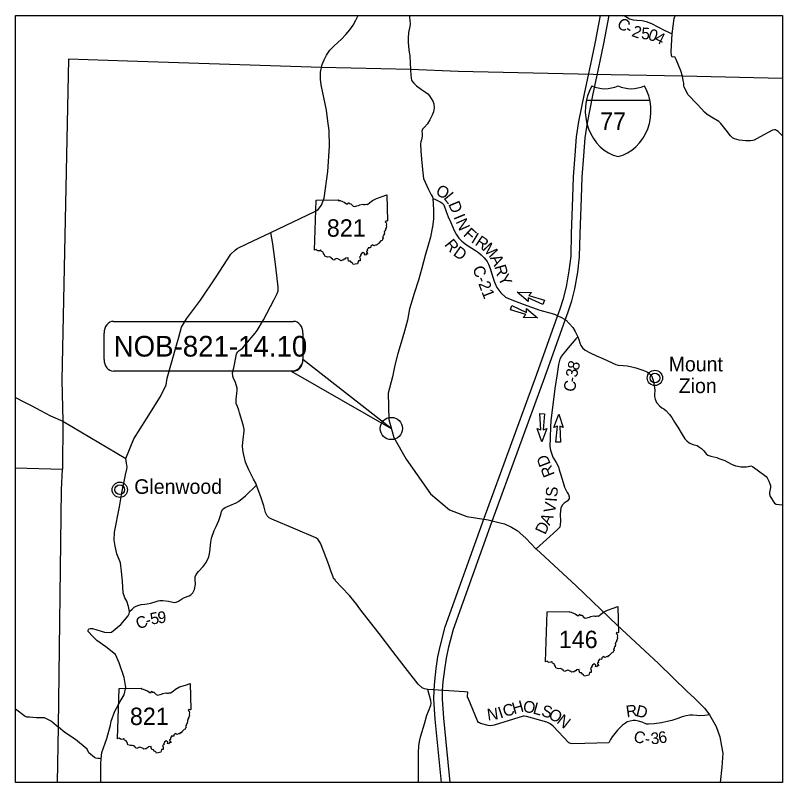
# Model space of a CAD drawing. Extents: x -452339 to 6403467, y -1 to 1814750.
# Drawn here: x 53877 to 93371, y 1551166 to 1590661 of the extents above; entities that cross this region are included whole.
import ezdxf

# ---------------------------------------------------------------- set-up
doc = ezdxf.new("R2010")
doc.units = 0
for name, color, linetype in [('Default', 7, 'Continuous'), ('GM_X_Adjacent_County_Text', 7, 'Continuous'), ('GM_X_County', 7, 'Continuous'), ('GM_X_County_Road', 7, 'Continuous'), ('GM_X_County_Road_Text', 7, 'Continuous'), ('GM_X_Minor_Lake_Text', 7, 'Continuous'), ('GM_X_Section_Text', 7, 'Continuous'), ('GM_X_Township_ROW', 7, 'Continuous')]:
    doc.layers.add(name, color=color, linetype=linetype)

msp = doc.modelspace()

# ---------------------------------------------------------------- linework, layer by layer
at = {"layer": 'Default'}
for p, q in [((53877, 1551166), (53877, 1590661)), ((53877, 1590661), (93371, 1590661)), ((93371, 1590661), (93371, 1551166)), ((69279, 1578571), (69362, 1581153)), ((79709, 1576407), (80444, 1576389)), ((80265, 1575926), (79709, 1576407)), ((80444, 1576389), (80309, 1576239)), ((80309, 1576239), (81106, 1575994)), ((80266, 1576128), (80265, 1575926)), ((81020, 1575773), (80266, 1576128)), ((81106, 1575994), (81020, 1575773)), ((79355, 1575504), (79440, 1575725)), ((80151, 1575258), (79355, 1575504)), ((79440, 1575725), (80195, 1575370)), ((80195, 1575370), (80195, 1575571)), ((80195, 1575571), (80751, 1575090)), ((80015, 1575109), (80151, 1575258)), ((80751, 1575090), (80015, 1575109)), ((80919, 1569326), (80873, 1570159)), ((80873, 1570159), (81110, 1570155)), ((81110, 1570155), (81039, 1569324)), ((81585, 1569451), (81843, 1570140)), ((81843, 1570140), (82082, 1569444)), ((81775, 1569521), (81585, 1569451)), ((81704, 1568690), (81775, 1569521)), ((82082, 1569444), (81894, 1569519)), ((81894, 1569519), (81941, 1568686)), ((80970, 1568706), (80732, 1569402)), ((80732, 1569402), (80919, 1569326)), ((81229, 1569394), (80970, 1568706)), ((81039, 1569324), (81229, 1569394)), ((81941, 1568686), (81704, 1568690)), ((81169, 1557385), (81252, 1559967)), ((59143, 1553424), (59226, 1556006)), ((93371, 1551166), (53877, 1551166))]:
    msp.add_line(p, q, dxfattribs=at)
for points in [[(85210, 1590661), (85358, 1590561), (85481, 1590488), (85671, 1590437), (85874, 1590419), (86133, 1590396), (86352, 1590345), (86618, 1590234), (87276, 1589890), (87684, 1589716)], [(88215, 1587527), (88127, 1587807), (87891, 1588388), (87819, 1588531), (87686, 1588501), (87643, 1588594), (87638, 1588794), (87684, 1589716), (87781, 1590504), (87818, 1590600), (87870, 1590661)], [(93371, 1584462), (93145, 1584676), (93054, 1584741), (93002, 1584766), (92946, 1584770), (92850, 1584743), (92216, 1584401), (91903, 1584244), (91831, 1584217), (91715, 1584202), (91484, 1584200), (91125, 1584240), (90886, 1584302), (90790, 1584359), (90684, 1584460), (90463, 1584758), (90266, 1585013), (90187, 1585101), (90080, 1585191), (89803, 1585361), (89485, 1585565), (89347, 1585678), (89216, 1585827), (88952, 1586114), (88509, 1586567), (88309, 1586966), (88290, 1587041), (88279, 1587162), (88255, 1587300), (88215, 1587527)], [(69362, 1581153), (70507, 1581170), (70489, 1581138), (70597, 1581132), (70711, 1581077), (70809, 1581042), (70927, 1580960), (70998, 1580961), (71028, 1581029), (71082, 1580976), (71147, 1580967), (71259, 1580843), (71351, 1580817), (71462, 1580859), (71544, 1580866), (71604, 1580908), (71761, 1580944), (71805, 1580922), (71888, 1580927), (71931, 1580943), (72003, 1580928), (72130, 1581023), (72262, 1581133), (72464, 1581238), (72766, 1581336), (73005, 1581425), (73040, 1580084)], [(75373, 1581231), (75473, 1581198), (75751, 1581067), (75830, 1581010), (75925, 1580901), (76045, 1580572), (76154, 1580290), (76295, 1579997), (76462, 1579591), (76568, 1579390), (76702, 1579200), (76860, 1579035), (77094, 1578852), (77506, 1578596), (77721, 1578458), (77851, 1578340), (78009, 1578175), (78155, 1577989), (78229, 1577848), (78315, 1577631), (78446, 1577178), (78535, 1576920), (78664, 1576651), (78865, 1576377), (79107, 1576162), (79349, 1576044), (80017, 1575801), (80880, 1575480), (81501, 1575318), (81660, 1575265), (81804, 1575199), (81989, 1575104), (82220, 1574967), (82386, 1574805), (82564, 1574595), (82690, 1574390), (82827, 1574108)], [(73040, 1580084), (73004, 1580066), (72949, 1580075), (72913, 1580038), (72959, 1579975), (72980, 1579908), (72961, 1579836), (72980, 1579775), (72967, 1579725), (72933, 1579674), (72921, 1579627), (72891, 1579576), (72893, 1579548), (72866, 1579526), (72871, 1579442), (72856, 1579396), (72861, 1579356), (72816, 1579345), (72826, 1579312), (72797, 1579286), (72804, 1579242), (72771, 1579214), (72802, 1579158), (72777, 1579140), (72756, 1579072), (72697, 1579058), (72582, 1578933), (72540, 1578886), (72495, 1578874), (72469, 1578825), (72412, 1578825), (72326, 1578791), (72270, 1578849), (72173, 1578780), (72162, 1578699), (72039, 1578701), (72043, 1578661), (72016, 1578649), (71991, 1578608), (72005, 1578536), (71948, 1578517), (71955, 1578475), (71992, 1578450), (72008, 1578369), (71947, 1578385), (71897, 1578318), (71845, 1578334), (71862, 1578391), (71774, 1578461), (71692, 1578405), (71649, 1578316), (71648, 1578257), (71586, 1578221), (71627, 1578137), (71619, 1578079), (71620, 1578024), (71544, 1578026), (71496, 1577878)], [(66283, 1566486), (66259, 1566574), (66141, 1566786), (65894, 1567272), (65731, 1567667), (65620, 1568111), (65583, 1568295), (65566, 1568495), (65595, 1568836), (65652, 1569269), (65655, 1569357), (65602, 1569585), (65410, 1570204), (65373, 1570344), (65307, 1570532), (65250, 1570683), (65246, 1570795), (65249, 1570912), (65283, 1571192), (65302, 1571365), (65293, 1571477), (65268, 1571593), (65186, 1571816), (65101, 1571972), (65077, 1572094), (65055, 1572255), (65118, 1572518), (65268, 1573225), (65285, 1573269), (65329, 1573337), (65402, 1573404), (65490, 1573468), (65591, 1573543), (65724, 1573713), (66213, 1574297), (66331, 1574440), (66655, 1574986), (67189, 1576001), (67360, 1576352), (67397, 1576484), (67399, 1576668), (67290, 1577710), (67126, 1578900), (67019, 1579488)], [(71496, 1577878), (71363, 1577850), (71271, 1577833), (71238, 1577900), (71172, 1577936), (71128, 1578003), (71033, 1578012), (71011, 1578106), (71000, 1578181), (70870, 1578162), (70835, 1578116), (70788, 1578104), (70761, 1578057), (70698, 1578053), (70630, 1578031), (70586, 1578077), (70476, 1578123), (70426, 1578146), (70321, 1578110), (70300, 1578066), (70217, 1578085), (70197, 1578134), (70147, 1578149), (70136, 1578200), (70029, 1578228), (69947, 1578217), (69803, 1578258), (69793, 1578326), (69744, 1578408), (69719, 1578466), (69628, 1578509), (69609, 1578577), (69580, 1578575), (69553, 1578547), (69451, 1578535), (69411, 1578562), (69354, 1578610), (69279, 1578571)], [(82827, 1574108), (82730, 1574009), (82245, 1573445), (82205, 1573399)], [(82827, 1574108), (82873, 1573980), (82931, 1573803), (82986, 1573674), (83064, 1573542), (83203, 1573424), (83461, 1573289), (83791, 1573134), (84117, 1572995), (84597, 1572770), (84788, 1572688), (84904, 1572659), (85155, 1572632), (85366, 1572618), (85546, 1572589), (85812, 1572510), (86123, 1572419), (86306, 1572341), (86413, 1572292), (86486, 1572245), (86558, 1572168), (86639, 1572082), (86671, 1571977), (86700, 1571883)], [(82205, 1573399), (82204, 1573398), (82087, 1573263), (81982, 1573112), (81905, 1572956), (81830, 1572693), (81773, 1572209), (81645, 1571448), (81512, 1570344), (81445, 1569802), (81415, 1569473), (81408, 1568936), (81396, 1568467), (81424, 1568272), (81550, 1567917), (81718, 1567652), (81826, 1567422), (81873, 1567274), (81941, 1567055), (82068, 1566617), (82144, 1566370), (82277, 1566108), (82347, 1566001), (82384, 1565877), (82383, 1565778), (82277, 1565655), (82130, 1565553), (82048, 1565463), (81951, 1565305), (81912, 1564992), (81935, 1564616), (81926, 1564448), (81900, 1564311), (81750, 1564164), (80689, 1563193)], [(86700, 1571883), (86726, 1571776), (86767, 1571504), (86786, 1571348), (86777, 1571144), (86775, 1571044), (86805, 1570900), (86884, 1570729), (87051, 1570552), (87161, 1570466), (87258, 1570407), (87359, 1570321), (87555, 1570112), (87666, 1569954), (87806, 1569728), (87974, 1569467), (88201, 1569090), (88340, 1568865), (88434, 1568758), (88552, 1568656), (88750, 1568564), (88970, 1568512), (89043, 1568477), (89201, 1568363), (89307, 1568249), (89376, 1568162), (89434, 1568083), (89523, 1568029), (89680, 1567968), (89985, 1567897), (90094, 1567855), (90391, 1567740), (90735, 1567554), (90944, 1567466), (91068, 1567452), (91225, 1567419), (91517, 1567424), (91680, 1567459), (91736, 1567468), (91817, 1567433), (92056, 1567261), (92517, 1566921), (92578, 1566858), (92665, 1566691), (92716, 1566552), (92741, 1566468), (92743, 1566356), (92706, 1566191), (92691, 1566103), (92697, 1566019), (92727, 1565903), (92957, 1565559), (93042, 1565505), (93186, 1565479), (93371, 1565463)], [(59746, 1559984), (59891, 1560096), (59999, 1560196), (60054, 1560241), (60178, 1560290), (60361, 1560340), (60549, 1560353), (60661, 1560370), (60857, 1560408), (61232, 1560523), (61320, 1560539), (61475, 1560541), (61756, 1560507), (61988, 1560453), (62072, 1560445), (62152, 1560454), (62275, 1560507), (62430, 1560608), (62586, 1560698), (62817, 1560788), (62917, 1560836), (63016, 1560933), (63091, 1561114), (63149, 1561387), (63131, 1561603), (63138, 1561755), (63185, 1561888), (63304, 1562029), (63542, 1562299), (63701, 1562493), (63830, 1562786), (63881, 1563043), (63933, 1563544), (63976, 1563756), (64105, 1564138), (64207, 1564351), (64353, 1564653), (64447, 1564974), (64482, 1565122), (64557, 1565235), (64672, 1565328), (64911, 1565426), (65238, 1565565), (65370, 1565638), (65719, 1565933), (66283, 1566486)], [(77176, 1555508), (77176, 1555510), (77155, 1555559), (77147, 1555611), (77161, 1555823), (76993, 1555838), (75649, 1555922), (75113, 1555955), (74945, 1555998), (74824, 1556053), (74619, 1556243), (73942, 1557099), (73308, 1557919), (72606, 1558839), (71775, 1559894), (71561, 1560184), (71452, 1560328), (71307, 1560531), (71081, 1560805), (70678, 1561219), (70364, 1561557), (70332, 1561600), (70259, 1561672), (70235, 1561764), (70133, 1562019), (70018, 1562375), (69733, 1563102), (69575, 1563497), (69518, 1563604), (69453, 1563696), (69349, 1563767), (68298, 1564215), (67079, 1564726), (66947, 1564801), (66830, 1564897), (66745, 1565076), (66659, 1565420), (66536, 1565831), (66365, 1566295), (66283, 1566486)], [(81252, 1559967), (82397, 1559984), (82380, 1559952), (82487, 1559946), (82602, 1559891), (82699, 1559856), (82817, 1559774), (82889, 1559775), (82919, 1559842), (82973, 1559790), (83038, 1559781), (83150, 1559657), (83242, 1559631), (83353, 1559673), (83434, 1559680), (83495, 1559722), (83652, 1559757), (83696, 1559736), (83779, 1559741), (83821, 1559756), (83894, 1559742), (84021, 1559836), (84152, 1559947), (84355, 1560051), (84656, 1560150), (84896, 1560239), (84930, 1558898)], [(84930, 1558898), (84895, 1558880), (84840, 1558888), (84803, 1558851), (84849, 1558788), (84870, 1558722), (84851, 1558649), (84870, 1558589), (84858, 1558538), (84823, 1558488), (84811, 1558440), (84782, 1558390), (84784, 1558362), (84756, 1558340), (84761, 1558256), (84747, 1558209), (84752, 1558169), (84706, 1558159), (84717, 1558126), (84688, 1558100), (84694, 1558056), (84661, 1558028), (84693, 1557972), (84668, 1557954), (84646, 1557885), (84588, 1557871), (84473, 1557747), (84431, 1557699), (84385, 1557688), (84359, 1557639), (84303, 1557639), (84216, 1557605), (84161, 1557663), (84064, 1557593), (84052, 1557513), (83930, 1557515), (83934, 1557475), (83907, 1557463), (83882, 1557422), (83896, 1557350), (83838, 1557331), (83845, 1557289), (83883, 1557264), (83899, 1557183), (83838, 1557199), (83788, 1557131), (83735, 1557147), (83752, 1557205), (83665, 1557274), (83583, 1557219), (83540, 1557130), (83539, 1557070), (83477, 1557035), (83517, 1556951), (83510, 1556893), (83511, 1556838), (83434, 1556840), (83387, 1556692)], [(83387, 1556692), (83254, 1556663), (83162, 1556647), (83129, 1556714), (83062, 1556750), (83019, 1556817), (82924, 1556826), (82901, 1556920), (82891, 1556995), (82760, 1556976), (82725, 1556930), (82679, 1556918), (82652, 1556871), (82589, 1556867), (82521, 1556845), (82477, 1556891), (82366, 1556937), (82316, 1556960), (82212, 1556924), (82190, 1556880), (82108, 1556899), (82088, 1556948), (82038, 1556963), (82027, 1557014), (81920, 1557042), (81838, 1557030), (81693, 1557072), (81684, 1557139), (81635, 1557222), (81610, 1557279), (81519, 1557322), (81500, 1557391), (81471, 1557389), (81444, 1557361), (81342, 1557348), (81302, 1557376), (81245, 1557424), (81169, 1557385)], [(59226, 1556006), (60371, 1556023), (60353, 1555991), (60461, 1555985), (60576, 1555930), (60673, 1555895), (60791, 1555813), (60862, 1555814), (60893, 1555882), (60947, 1555829), (61012, 1555820), (61123, 1555696), (61216, 1555670), (61326, 1555712), (61408, 1555719), (61468, 1555761), (61625, 1555797), (61670, 1555775), (61753, 1555780), (61795, 1555795), (61868, 1555781), (61994, 1555875), (62126, 1555986), (62329, 1556090), (62630, 1556189), (62869, 1556278), (62904, 1554937)], [(74630, 1551166), (74623, 1551758), (74636, 1552699), (74650, 1553068), (74684, 1553284), (74754, 1553577), (74937, 1554199), (75062, 1554645), (75145, 1554838), (75267, 1555151), (75286, 1555251), (75265, 1555395), (75175, 1555707), (75113, 1555955)], [(89606, 1554657), (89360, 1554625), (89104, 1554611), (88960, 1554622), (88748, 1554644), (88596, 1554639), (88412, 1554613), (88205, 1554560), (87982, 1554474), (87662, 1554363), (87423, 1554313), (87132, 1554239), (86756, 1554192), (86460, 1554170), (86360, 1554185), (86132, 1554283), (85955, 1554338), (85803, 1554365), (85675, 1554360), (85528, 1554335), (85376, 1554289), (85276, 1554236), (85125, 1554123), (84879, 1553873), (84590, 1553522), (84507, 1553385), (84452, 1553285), (84420, 1553208), (82569, 1553166), (82469, 1553177), (82369, 1553220), (81555, 1554071), (81463, 1554163), (81378, 1554214), (81230, 1554285), (80180, 1554577), (80072, 1554592), (80008, 1554584), (78524, 1554131), (78357, 1554098), (78213, 1554101), (77824, 1554206), (77772, 1554238), (77723, 1554265), (77659, 1554353), (77176, 1555508)], [(53877, 1554959), (54379, 1554594), (54448, 1554555), (54612, 1554554), (54957, 1554512), (55356, 1554515), (55744, 1554329), (56091, 1554024)], [(62904, 1554937), (62869, 1554919), (62814, 1554927), (62777, 1554890), (62823, 1554828), (62844, 1554761), (62825, 1554688), (62844, 1554628), (62831, 1554577), (62797, 1554527), (62785, 1554480), (62755, 1554429), (62757, 1554401), (62730, 1554379), (62735, 1554295), (62721, 1554249), (62726, 1554208), (62680, 1554198), (62691, 1554165), (62662, 1554139), (62668, 1554095), (62635, 1554067), (62667, 1554011), (62641, 1553993), (62620, 1553925), (62562, 1553910), (62446, 1553786), (62405, 1553738), (62359, 1553727), (62333, 1553678), (62277, 1553678), (62190, 1553644), (62134, 1553702), (62037, 1553633), (62026, 1553552), (61903, 1553554), (61908, 1553514), (61880, 1553502), (61856, 1553461), (61870, 1553389), (61812, 1553370), (61819, 1553328), (61856, 1553303), (61873, 1553222), (61811, 1553238), (61761, 1553171), (61709, 1553187), (61726, 1553244), (61639, 1553313), (61556, 1553258), (61513, 1553169), (61513, 1553110), (61451, 1553074), (61491, 1552990), (61483, 1552932), (61485, 1552877), (61408, 1552879), (61361, 1552731)], [(58298, 1552388), (58188, 1552408), (58122, 1552414), (58018, 1552427), (57950, 1552459), (57656, 1552697), (57576, 1552896), (56966, 1553387), (56419, 1553752), (56091, 1554024)], [(61361, 1552731), (61228, 1552702), (61135, 1552686), (61102, 1552753), (61036, 1552789), (60993, 1552856), (60897, 1552865), (60875, 1552959), (60864, 1553034), (60734, 1553015), (60699, 1552969), (60652, 1552957), (60626, 1552910), (60562, 1552906), (60495, 1552884), (60450, 1552930), (60340, 1552976), (60290, 1552999), (60186, 1552963), (60164, 1552919), (60082, 1552938), (60062, 1552987), (60012, 1553002), (60001, 1553053), (59894, 1553081), (59811, 1553070), (59667, 1553111), (59658, 1553179), (59608, 1553261), (59584, 1553318), (59492, 1553361), (59473, 1553430), (59444, 1553428), (59418, 1553400), (59316, 1553387), (59275, 1553415), (59218, 1553463), (59143, 1553424)]]:
    msp.add_lwpolyline(points, dxfattribs=at)
for centre, major_axis, start_param, end_param in [((85392, 1585748), (0, -2422), 4.15077, 6.05619), ((84224, 1588818), (0, -1932), 5.88324, 6.683049), ((84411, 1585748), (0, -2422), 0.227007, 2.13242), ((85578, 1588819), (0, -1933), 5.883359, 6.683012)]:
    msp.add_ellipse(centre, major_axis=major_axis, ratio=0.9, start_param=start_param, end_param=end_param, dxfattribs=at)
at = {"layer": 'GM_X_County_Road'}
for points in [[(69631, 1587971), (69670, 1588131), (69765, 1588372), (69886, 1588617), (70066, 1588868), (70281, 1589098), (70667, 1589434), (70887, 1589674), (71088, 1589915), (71258, 1590155), (71404, 1590410), (71526, 1590661)], [(74144, 1590661), (74167, 1590564), (74197, 1590217), (74179, 1590085), (74119, 1589775), (74089, 1589494), (74098, 1589258), (74138, 1588878), (74183, 1588557), (74223, 1587875)], [(83397, 1587667), (83554, 1588393), (83730, 1589294), (83904, 1590204), (84001, 1590661)], [(83827, 1587574), (83985, 1588305), (84162, 1589211), (84439, 1590661)], [(59565, 1567850), (59978, 1568862), (60623, 1569900), (61344, 1571042), (61634, 1571649), (61689, 1571994), (62168, 1573691), (62286, 1574096), (62437, 1574614), (62693, 1575047), (63414, 1576007), (64219, 1577195), (64969, 1578369), (65187, 1578579), (65287, 1578658), (65785, 1578905), (67019, 1579488), (69287, 1580557), (69461, 1580675), (69643, 1580898), (69779, 1581248), (69957, 1582622), (70048, 1583926), (70032, 1584733), (69967, 1585209), (69886, 1585785), (69613, 1587090), (69580, 1587368), (69576, 1587556), (69591, 1587741), (69631, 1587971)], [(74223, 1587875), (74238, 1587571), (74245, 1587467), (74251, 1587409), (74263, 1587344), (74283, 1587288), (74383, 1587164), (74532, 1587026), (74790, 1586847), (74988, 1586714), (75100, 1586625), (75191, 1586518), (75280, 1586384), (75360, 1586245), (75413, 1586098), (75436, 1585902), (75405, 1585702), (75338, 1585519), (75212, 1585280), (75096, 1585085), (74942, 1584909), (74838, 1584802), (74803, 1584704), (74813, 1584569), (74810, 1584434), (74778, 1584258), (74753, 1584154), (74731, 1584041), (74750, 1583685), (74785, 1583256), (74829, 1582721), (74890, 1582268), (75059, 1581881), (75150, 1581697), (75283, 1581428), (75342, 1581327), (75373, 1581231), (75399, 1580654), (75403, 1580187), (75344, 1579755), (75344, 1579752)], [(78008, 1564774), (80722, 1572188), (81782, 1575177), (81914, 1575551), (82099, 1576085), (82249, 1576682), (82390, 1577503), (82480, 1578262), (82510, 1579426), (82575, 1581277), (82607, 1582352), (82699, 1583466), (82761, 1584400), (82888, 1585205), (83175, 1586625), (83397, 1587667)], [(78421, 1564622), (81136, 1572039), (82196, 1575030), (82330, 1575406), (82521, 1575959), (82680, 1576591), (82825, 1577440), (82919, 1578230), (82950, 1579413), (83015, 1581263), (83046, 1582327), (83137, 1583434), (83199, 1584351), (83321, 1585128), (83606, 1586535), (83828, 1587575)], [(75344, 1579752), (75337, 1579702), (75246, 1579248), (74965, 1578300), (74793, 1577649), (74621, 1577026), (74401, 1576338), (74235, 1575775), (74170, 1575555), (74053, 1574972), (73908, 1574410), (73739, 1573815), (73569, 1573256), (73413, 1572654), (73296, 1572048), (73070, 1571221), (73105, 1569860), (73353, 1568931), (73989, 1567817), (75239, 1566025), (76221, 1565210), (77107, 1564869), (78215, 1564698), (78832, 1564536), (79059, 1564490), (79412, 1564310), (79701, 1564144), (80147, 1563753), (80674, 1563207), (80689, 1563193), (82745, 1561292), (84852, 1559278), (86987, 1557300), (86999, 1557288), (88455, 1555855), (88814, 1555538), (89373, 1554985), (89606, 1554657), (89879, 1554184), (89952, 1554057), (90131, 1553527), (90229, 1553041), (90290, 1552685), (90233, 1551955), (90156, 1551166)], [(53877, 1570985), (54308, 1570770), (54718, 1570559), (55180, 1570313), (55678, 1570043), (56319, 1569768)], [(56319, 1569768), (59565, 1567850)], [(58284, 1551166), (58271, 1551875), (58277, 1552152), (58298, 1552388), (58328, 1552717), (58582, 1553440), (58776, 1554118), (58803, 1554334), (59005, 1554845), (59267, 1555348), (59471, 1555685), (59558, 1556063), (59480, 1556576), (59224, 1557332), (59030, 1557768), (58528, 1558151), (58078, 1558489), (57817, 1558744), (57676, 1558888), (57628, 1558952), (57624, 1559016), (57667, 1559081), (57727, 1559105), (57855, 1559101), (58293, 1558963), (58461, 1558904), (58712, 1558893), (58832, 1558910), (59308, 1559302), (59678, 1559749), (59733, 1559854), (59752, 1559950), (59746, 1559984), (59698, 1560233), (59609, 1560509), (59512, 1560685), (59423, 1560937), (59385, 1561518), (59335, 1562055), (59314, 1562332), (59293, 1562480), (59103, 1562940), (59013, 1563337), (58956, 1563645), (58975, 1564054), (59230, 1565370), (59320, 1565876), (59365, 1566091), (59552, 1567004), (59613, 1567295), (59635, 1567401), (59602, 1567613), (59565, 1567850)], [(75815, 1551166), (75487, 1554442), (75424, 1555457), (75429, 1555931), (75463, 1556397), (75543, 1557046), (75629, 1557648), (75757, 1558250), (76004, 1559192), (78008, 1564772)], [(76257, 1551166), (75926, 1554477), (75864, 1555468), (75869, 1555912), (75901, 1556355), (75979, 1556988), (76062, 1557571), (76186, 1558149), (76424, 1559062), (78422, 1564624)]]:
    msp.add_lwpolyline(points, dxfattribs=at)
at = {"layer": 'GM_X_County_Road_Text'}
for centre, radius in [((86796, 1571997), 393), ((86796, 1571997), 249), ((59252, 1566243), 393), ((59252, 1566243), 249)]:
    msp.add_circle(centre, radius, dxfattribs=at)
at = {"layer": 'GM_X_Minor_Lake_Text'}
msp.add_line((83272, 1586293), (86534, 1586293), dxfattribs=at)
at = {"layer": 'GM_X_Section_Text'}
for p, q in [((56615, 1588407), (56272, 1571887)), ((59648, 1588306), (56615, 1588407)), ((69631, 1587971), (59648, 1588306)), ((74223, 1587875), (69631, 1587971)), ((76665, 1587777), (74223, 1587875)), ((83612, 1587621), (76665, 1587777)), ((88215, 1587527), (83612, 1587621)), ((93371, 1587406), (88215, 1587527)), ((56272, 1571887), (56319, 1569768)), ((56319, 1569768), (56306, 1567305)), ((53877, 1567370), (56306, 1567305)), ((56256, 1566238), (56306, 1567305)), ((56256, 1566238), (56306, 1567305)), ((56256, 1566238), (56306, 1567305)), ((56091, 1554024), (56256, 1566238)), ((56091, 1554024), (56256, 1566238)), ((56052, 1551166), (56091, 1554024))]:
    msp.add_line(p, q, dxfattribs=at)
at = {"layer": 'GM_X_Township_ROW'}
for p, q in [((73229, 1569396), (68681, 1572949)), ((68081, 1572349), (73229, 1569396))]:
    msp.add_line(p, q, dxfattribs=at)
for points in [[(58921, 1574909), (68201, 1574909)], [(58441, 1572949), (58441, 1574309)], [(68681, 1574309), (68681, 1572949)], [(68201, 1572349), (58921, 1572349)]]:
    msp.add_lwpolyline(points, dxfattribs=at)
msp.add_circle((73229, 1569396), 572, dxfattribs=at)
msp.add_arc((68081, 1572949), 600, 270, 0, dxfattribs=at)
for centre, major_axis, start_param, end_param in [((58921, 1574309), (0, -600), 3.141593, 4.712389), ((68201, 1574309), (0, 600), 4.712389, 6.283185), ((58921, 1572949), (0, -600), 4.712389, 6.283185), ((68201, 1572949), (0, 600), 3.141593, 4.712389)]:
    msp.add_ellipse(centre, major_axis=major_axis, ratio=0.8, start_param=start_param, end_param=end_param, dxfattribs=at)

# ---------------------------------------------------------------- texts
at = {"layer": 'Default'}
for s, p in [('77', (83975, 1584766)), ('821', (69910, 1579268)), ('146', (81849, 1558092)), ('821', (59774, 1554131))]:
    msp.add_text(s, height=895.5, dxfattribs=at).set_placement(p)
at = {"layer": 'GM_X_Adjacent_County_Text'}
for s, p in [('Mount', (87506, 1572335)), ('Zion', (88025, 1571219)), ('Glenwood', (60000, 1566032))]:
    msp.add_text(s, height=750, rotation=0, dxfattribs=at).set_placement(p)
at = {"layer": 'GM_X_County'}
for s, rotation, p in [('C', 324.6048, (84788, 1590108)), ('2', 340.7081, (85559, 1589603)), ('-', 326.6535, (85209, 1589810)), ('5', 355.429, (86072, 1589446)), ('0', 341.895, (86404, 1589424)), ('4', 333.6142, (86734, 1589318)), ('O', 333.2183, (75469, 1581453)), ('L', 308.7421, (75888, 1581258)), ('D', 293.013, (76147, 1580945)), ('I', 292.2949, (76423, 1580289)), ('N', 294.0168, (76524, 1580043)), ('F', 317.8384, (76897, 1579342)), ('I', 328.6139, (77296, 1578997)), ('R', 308.5227, (75933, 1578850)), ('R', 325.7882, (77500, 1578873)), ('D', 324.605, (76371, 1578340)), ('M', 312.863, (77880, 1578619)), ('A', 296.6433, (78298, 1578178)), ('R', 286.0151, (78524, 1577734)), ('C-21', 291.1524, (77393, 1577640)), ('Y', 295.5868, (78699, 1577158)), ('8', 72.1493, (82837, 1572342)), ('3', 82.7498, (82797, 1572004)), ('-', 80.9845, (82756, 1571741)), ('C', 80.5787, (82674, 1571250)), ('RD', 111.4284, (81654, 1567028)), ('S', 85.4814, (81768, 1565851)), ('V', 79.2362, (81642, 1565010)), ('I', 86.0564, (81751, 1565606)), ('A', 65.3128, (81373, 1564379)), ('D', 64.9811, (81148, 1563897)), ('C', 21.1349, (60212, 1559044)), ('5', 11.5896, (60881, 1559291)), ('9', 5.2261, (61225, 1559362)), ('-', 17.9532, (60663, 1559219)), ('H', 15.7673, (79537, 1554681)), ('O', 350.1304, (79974, 1554821)), ('L', 344.5261, (80480, 1554734)), ('N', 7.6397, (78195, 1554361)), ('I', 18.5685, (78839, 1554460)), ('C', 17.0944, (79069, 1554537)), ('S', 343.821, (80910, 1554614)), ('O', 329.9384, (81264, 1554517)), ('R', 8.3189, (85350, 1554524)), ('D', 346.0159, (85777, 1554599)), ('N', 321.8215, (81702, 1554265)), ('C', 345.1591, (85653, 1553290)), ('3', 5.0048, (86601, 1553136)), ('6', 9.4377, (87020, 1553175)), ('-', 358.2349, (86277, 1553142))]:
    msp.add_text(s, height=600, rotation=rotation, dxfattribs=at).set_placement(p)
at = {"layer": 'GM_X_Township_ROW'}
msp.add_text('NOB-821-14.10', height=1063.82, dxfattribs=at).set_placement((58938, 1573097))

doc.saveas('drawing.dxf')
